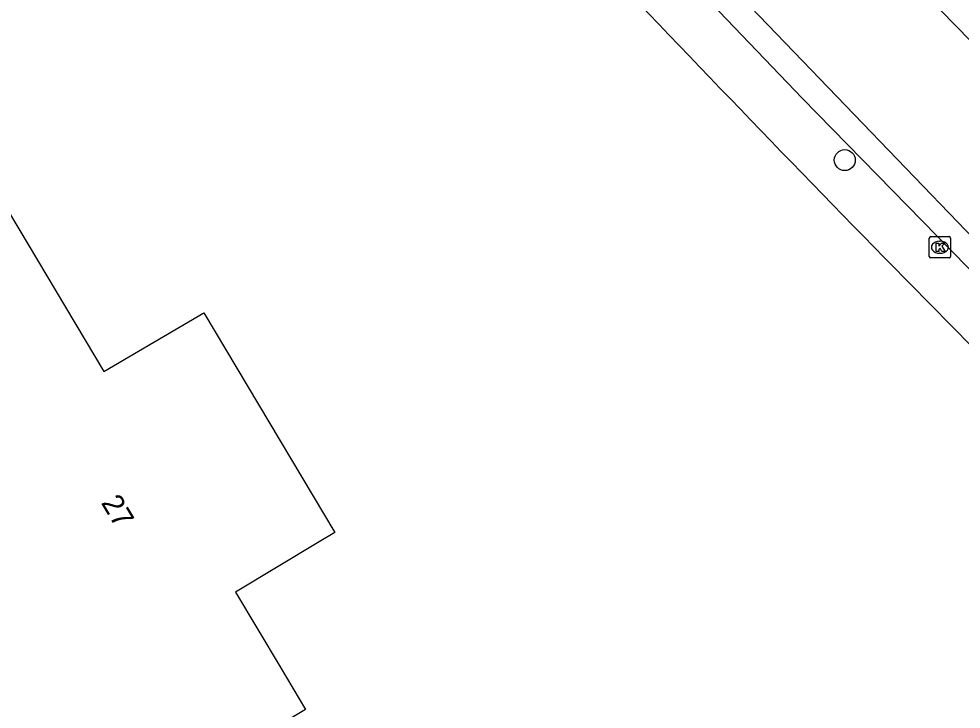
# Model space of a CAD drawing. Extents: x 157692 to 159670, y 381454 to 383289.
# Drawn here: x 157857.31 to 157901.41, y 382930.61 to 382962.91 of the extents above; entities that cross this region are included whole.
import ezdxf

# ---------------------------------------------------------------- set-up
doc = ezdxf.new("R2010")
doc.units = 0
for name, color, linetype in [('IMGEO_Boom', 7, 'Continuous'), ('IMGEO_Kolk', 7, 'Continuous'), ('IMGEO_Pand', 7, 'Continuous'), ('IMGEO_Pand_nummerreeks', 7, 'Continuous'), ('IMGEO_Rijbaan_lokaal_gesloten', 7, 'Continuous'), ('IMGEO_Voetpad_open', 7, 'Continuous')]:
    doc.layers.add(name, color=color, linetype=linetype)

msp = doc.modelspace()

# ---------------------------------------------------------------- linework, layer by layer
at = {"layer": 'IMGEO_Boom'}
msp.add_circle((157895.966, 382956.297), 0.489, dxfattribs=at)
at = {"layer": 'IMGEO_Kolk'}
for p, q in [((157899.919, 382951.792), (157899.919, 382952.644)), ((157899.994, 382952.718), (157900.846, 382952.718)), ((157900.407, 382952.498), (157900.432, 382952.498)), ((157900.92, 382952.644), (157900.92, 382951.792)), ((157900.43, 382951.938), (157900.405, 382951.938)), ((157900.846, 382951.718), (157899.994, 382951.718))]:
    msp.add_line(p, q, dxfattribs=at)
for points in [[(157899.919, 382951.792), (157899.919, 382952.644)], [(157899.994, 382952.718), (157900.846, 382952.718)], [(157900.24, 382952.418), (157900.363, 382952.418), (157900.363, 382952.267), (157900.493, 382952.418), (157900.657, 382952.418), (157900.511, 382952.267), (157900.664, 382952.018), (157900.512, 382952.018), (157900.427, 382952.182), (157900.363, 382952.115), (157900.363, 382952.018), (157900.24, 382952.018), (157900.24, 382952.418)], [(157900.92, 382952.644), (157900.92, 382951.792)], [(157900.846, 382951.718), (157899.994, 382951.718)]]:
    msp.add_lwpolyline(points, dxfattribs=at)
for centre, start, end in [((157899.996, 382952.642), 91.552, 178.448), ((157899.996, 382952.642), 91.552, 178.448), ((157900.844, 382952.642), 1.552, 88.448), ((157900.844, 382952.642), 1.552, 88.448), ((157899.996, 382951.794), 181.552, 268.448), ((157899.996, 382951.794), 181.552, 268.448), ((157900.844, 382951.794), 271.552, 358.448), ((157900.844, 382951.794), 271.552, 358.448)]:
    msp.add_arc(centre, 0.0765, start, end, dxfattribs=at)
for centre, major_axis, ratio, start_param, end_param in [((157900.406, 382952.218), (-0.387, 0.002), 0.722429, 4.712389, 7.853982), ((157900.431, 382952.218), (-0.39, 0.002), 0.717154, 1.570796, 4.712389)]:
    msp.add_ellipse(centre, major_axis=major_axis, ratio=ratio, start_param=start_param, end_param=end_param, dxfattribs=at)
at = {"layer": 'IMGEO_Pand'}
msp.add_lwpolyline([(157837.696, 382985.979), (157861.292, 382946.403), (157865.252, 382948.73), (157865.961, 382949.146), (157872.102, 382938.879), (157871.371, 382938.438), (157867.457, 382936.077), (157869.534, 382932.592), (157870.723, 382930.596), (157869.088, 382929.615), (157892.338, 382890.702), (157881.236, 382884.048), (157834.534, 382856.047), (157832.235, 382859.881), (157783.62, 382831.274)], dxfattribs=at)
at = {"layer": 'IMGEO_Rijbaan_lokaal_gesloten'}
for points in [[(157947.967, 382910.552), (157946.644, 382911.702), (157931.39, 382924.697), (157917.745, 382937.164), (157901.645, 382952.982), (157887.528, 382967.671), (157876.832, 382979.322), (157871.708, 382985.081), (157860.333, 382998.307), (157856.331, 383002.954), (157848.451, 383012.068), (157848.333, 383012.223), (157843.229, 383018.142), (157838.644, 383023.478), (157833.658, 383029.315), (157818.224, 383047.235), (157807.775, 383059.411), (157802.275, 383065.844)], [(157850.521, 383024.905), (157853.541, 383017.962), (157856.251, 383014.213), (157856.467, 383013.904), (157862.032, 383006.673), (157867.395, 382999.837), (157867.54, 382999.666), (157867.971, 382999.126), (157869.317, 382997.443), (157870.868, 382995.617), (157882.451, 382982.543), (157892.691, 382971.484), (157900.441, 382963.318), (157907.565, 382956.05), (157922.939, 382941.093), (157929.386, 382935.17), (157936.105, 382929.105), (157938.637, 382926.944)], [(157880.505, 382973.291), (157884.414, 382969.188), (157893.988, 382959.187), (157903.105, 382949.871), (157911.795, 382941.344), (157919.191, 382934.261), (157926.716, 382927.298), (157940.793, 382914.946), (157946.658, 382909.821)]]:
    msp.add_lwpolyline(points, dxfattribs=at)
msp.add_arc((158379.787, 383426.039), 664.845, 223.019482, 226.707844, dxfattribs=at)
at = {"layer": 'IMGEO_Voetpad_open'}
msp.add_arc((158701.069, 383738.472), 1124.351, 222.857272, 225.107447, dxfattribs=at)

# ---------------------------------------------------------------- texts
at = {"layer": 'IMGEO_Pand_nummerreeks'}
msp.add_text('27', height=1, rotation=300.8387, dxfattribs=at).set_placement((157861.136, 382940.267))

doc.saveas('drawing.dxf')
